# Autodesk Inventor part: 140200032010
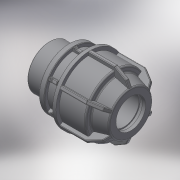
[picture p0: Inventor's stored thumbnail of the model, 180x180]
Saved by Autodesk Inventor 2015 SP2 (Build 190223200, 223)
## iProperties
Created: 2017-08
Part Number: 140200032010
Material: Generic
Description: PLASSON L.14 MALE ADAPTOR (SILVER) 32-1''
Document SubType Name: Modeling
Designer: KIM
Density: 1 g/cm^3
Appearance: Default
Author: KIM
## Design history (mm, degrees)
derived "140200.ipt"
feature "Solid1::140200.ipt"
tag "TaggingFeature1"
body "Solid1"
other parameters: "d1" = 32, "d4" = 15 deg, "d5" = 39.6, "d6" = 13.068, "d10" = 61, "d16" = 32.64, "d17" = 3, "d18" = 84, "d19" = 5.4, "d21" = 5.4, "d22" = 39.8988, "d24" = 3, "d25" = 54.9, "d26" = 45.75, "d27" = 3, "d28" = 135 deg, "d29" = 1.8, "d31" = 1.6, "d44" = 0.64, "d45" = 0.96, "d46" = 150 deg, "d49" = 3.05, "d50" = 0, "d51" = 1.83, "d52" = 1.22, "d53" = 45 deg, "d54" = 21, "d55" = 8.4, "d56" = 3.05, "d57" = 0, "d58" = 0.96, "d59" = 0.64, "d61" = 360 deg, "d63" = 33.249, "d64" = 25.6, "d65" = 18, "d66" = 44.88615, "d_" = 32, "R_" = 33.249, "E_" = 61, "H_" = 84, "l_2" = 18
